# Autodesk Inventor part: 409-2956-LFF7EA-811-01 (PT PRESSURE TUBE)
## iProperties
Created: 2010-09
Part Number: 409-2956-LFF7EA-811-01 (PT PRESSURE TUBE)
Material: 3/8" OD TUBE - SS
Document SubType Name: Modeling
Designer: S. Boerckel
Engineer: Steve Boerckel
Mass: 15.0126 g
Surface Area: 31.4303 cm^2
Volume: 1.85799 cm^3
Density: 8.08 g/cm^3
Description: PT TUBE
LGTH: 6.977 in
Author: S. Boerckel
Revision Number: 0
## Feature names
1. Sweep2
